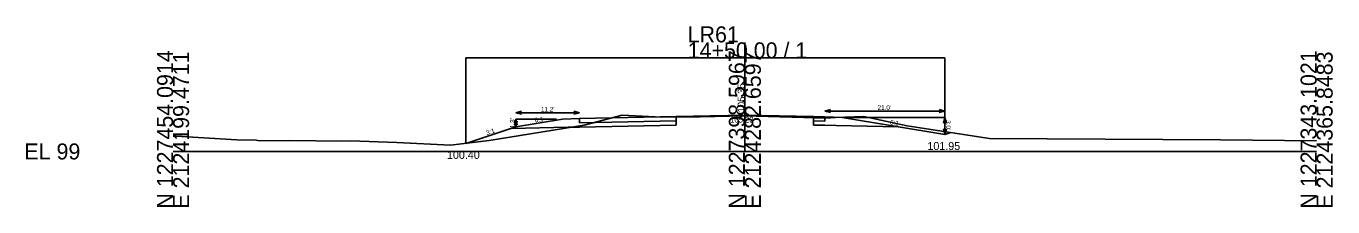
# Model space of a CAD drawing. Extents: x 2126751 to 2128979, y 1225108 to 1234639.
# Drawn here: x 2127750.9 to 2127979.4, y 1229607.5 to 1229639.1 of the extents above; entities that cross this region are included whole.
import ezdxf

# ---------------------------------------------------------------- set-up
doc = ezdxf.new("R2010")
doc.units = 0
for name, color, linetype in [('XS_CELL', 7, 'Continuous'), ('XS_M_DITCH', 7, 'Continuous'), ('XS_P_FINISHED_GRADE', 7, 'Continuous'), ('XS_P_FINISHED_GRADE_ELEV_TX', 7, 'Continuous'), ('XS_P_SUBGRADE_GRANULAR', 7, 'Continuous'), ('XS_P_SUBGRADE_LEVELING', 7, 'Continuous'), ('XS_P_SUBGRADE_PAVEMENT', 7, 'Continuous'), ('XS_P_TX_CLEARZONE', 7, 'Continuous'), ('XS_P_TX_DCH', 7, 'Continuous'), ('XS_P_TX_FS_BS', 7, 'Continuous'), ('XS_X_GROUND', 7, 'Continuous'), ('XS_X_GROUND_TX', 7, 'Continuous')]:
    doc.layers.add(name, color=color, linetype=linetype)

msp = doc.modelspace()

# ---------------------------------------------------------------- linework, layer by layer
at = {"layer": 'XS_CELL'}
for p, q in [((2127876.61, 1229617.21), (2127876.61, 1229636.29)), ((2127776.61, 1229617.21), (2127876.61, 1229617.21)), ((2127876.61, 1229617.21), (2127976.61, 1229617.21))]:
    msp.add_line(p, q, dxfattribs=at)
at = {"layer": 'XS_M_DITCH'}
for p, q in [((2127827.82, 1229618.61), (2127827.82, 1229633.56)), ((2127827.82, 1229633.56), (2127911.61, 1229633.56)), ((2127911.61, 1229633.56), (2127911.61, 1229620.16))]:
    msp.add_line(p, q, dxfattribs=at)
at = {"layer": 'XS_P_FINISHED_GRADE'}
for p, q in [((2127844.71, 1229622.86), (2127836.56, 1229621.51)), ((2127847.72, 1229622.98), (2127844.71, 1229622.86)), ((2127864.61, 1229623.32), (2127847.72, 1229622.98)), ((2127864.61, 1229623.32), (2127876.61, 1229623.56)), ((2127876.61, 1229623.56), (2127888.61, 1229623.32)), ((2127888.61, 1229623.32), (2127890.61, 1229623.28)), ((2127890.61, 1229623.28), (2127893.61, 1229623.16)), ((2127893.61, 1229623.16), (2127911.61, 1229620.16)), ((2127836.56, 1229621.51), (2127827.82, 1229618.61)), ((2127911.61, 1229620.16), (2127912.63, 1229620.5))]:
    msp.add_line(p, q, dxfattribs=at)
at = {"layer": 'XS_P_SUBGRADE_GRANULAR'}
for p, q in [((2127864.61, 1229621.82), (2127864.61, 1229622.57)), ((2127888.61, 1229621.82), (2127888.61, 1229622.57)), ((2127845.72, 1229621.44), (2127835.75, 1229621.24)), ((2127847.72, 1229621.48), (2127845.72, 1229621.44)), ((2127864.61, 1229621.82), (2127847.72, 1229621.48)), ((2127888.61, 1229621.82), (2127890.61, 1229621.78)), ((2127890.61, 1229621.78), (2127892.61, 1229621.74)), ((2127892.61, 1229621.74), (2127903.43, 1229621.52))]:
    msp.add_line(p, q, dxfattribs=at)
at = {"layer": 'XS_P_SUBGRADE_LEVELING'}
for p, q in [((2127864.61, 1229623.32), (2127864.61, 1229623.22)), ((2127864.61, 1229623.22), (2127868.77, 1229623.29)), ((2127868.77, 1229623.29), (2127876.48, 1229623.44)), ((2127876.48, 1229623.44), (2127886.94, 1229623.13)), ((2127886.94, 1229623.13), (2127888.61, 1229623.08)), ((2127888.61, 1229623.32), (2127888.61, 1229623.08))]:
    msp.add_line(p, q, dxfattribs=at)
at = {"layer": 'XS_P_SUBGRADE_PAVEMENT'}
for p, q in [((2127847.72, 1229622.23), (2127847.72, 1229622.98)), ((2127864.61, 1229622.57), (2127847.72, 1229622.23)), ((2127864.61, 1229622.57), (2127864.61, 1229623.22)), ((2127888.61, 1229622.57), (2127888.61, 1229623.08)), ((2127888.61, 1229622.57), (2127890.61, 1229622.53)), ((2127890.61, 1229622.53), (2127890.61, 1229623.28))]:
    msp.add_line(p, q, dxfattribs=at)
at = {"layer": 'XS_P_TX_CLEARZONE'}
for p, q in [((2127836.56, 1229623.98), (2127837.57, 1229624.23)), ((2127847.72, 1229623.98), (2127846.72, 1229624.23)), ((2127890.61, 1229624.28), (2127891.61, 1229624.53)), ((2127890.61, 1229624.28), (2127891.61, 1229624.03)), ((2127890.61, 1229624.28), (2127911.61, 1229624.28)), ((2127911.61, 1229624.28), (2127910.61, 1229624.53)), ((2127911.61, 1229624.28), (2127910.61, 1229624.03)), ((2127836.56, 1229622.86), (2127836.31, 1229621.86)), ((2127836.56, 1229621.51), (2127836.31, 1229622.51)), ((2127836.56, 1229623.98), (2127837.57, 1229623.73)), ((2127847.72, 1229623.98), (2127836.56, 1229623.98)), ((2127836.56, 1229622.86), (2127836.82, 1229621.86)), ((2127836.56, 1229622.86), (2127836.56, 1229621.51)), ((2127843.7, 1229622.86), (2127836.56, 1229622.86)), ((2127836.56, 1229621.51), (2127836.82, 1229622.51)), ((2127847.72, 1229623.98), (2127846.72, 1229623.73)), ((2127894.61, 1229623.16), (2127911.61, 1229623.16)), ((2127911.61, 1229623.16), (2127911.36, 1229622.16)), ((2127911.61, 1229623.16), (2127911.61, 1229620.16)), ((2127911.61, 1229623.16), (2127911.86, 1229622.16)), ((2127911.61, 1229620.16), (2127911.36, 1229621.16)), ((2127911.61, 1229620.16), (2127911.86, 1229621.16))]:
    msp.add_line(p, q, dxfattribs=at)
at = {"layer": 'XS_X_GROUND'}
for p, q in [((2127848.5, 1229621.81), (2127855.18, 1229623.57)), ((2127855.18, 1229623.57), (2127857.51, 1229623.45)), ((2127857.51, 1229623.45), (2127862.08, 1229623.18)), ((2127862.08, 1229623.18), (2127868.77, 1229623.29)), ((2127868.77, 1229623.29), (2127876.48, 1229623.44)), ((2127876.48, 1229623.44), (2127886.94, 1229623.13)), ((2127886.94, 1229623.13), (2127890.69, 1229623.02)), ((2127890.69, 1229623.02), (2127892.47, 1229623.12)), ((2127892.47, 1229623.12), (2127897.4, 1229623.31)), ((2127897.4, 1229623.31), (2127905.01, 1229621.67)), ((2127776.61, 1229619.87), (2127777.15, 1229619.86)), ((2127777.15, 1229619.86), (2127787.74, 1229619.24)), ((2127831.88, 1229619.1), (2127848.5, 1229621.81)), ((2127905.01, 1229621.67), (2127919.37, 1229619.46)), ((2127787.74, 1229619.24), (2127791.16, 1229619.16)), ((2127791.16, 1229619.16), (2127791.71, 1229619.09)), ((2127791.71, 1229619.09), (2127797.01, 1229619.1)), ((2127797.01, 1229619.1), (2127806.14, 1229618.99)), ((2127806.14, 1229618.99), (2127807.62, 1229619.04)), ((2127807.62, 1229619.04), (2127815.74, 1229618.8)), ((2127815.74, 1229618.8), (2127825.15, 1229618.3)), ((2127825.15, 1229618.3), (2127831.88, 1229619.1)), ((2127919.37, 1229619.46), (2127959.8, 1229619.26)), ((2127959.8, 1229619.26), (2127976.61, 1229619.09))]:
    msp.add_line(p, q, dxfattribs=at)

# ---------------------------------------------------------------- texts
at = {"layer": 'XS_CELL'}
for s, p in [('LR61', (2127866.61, 1229636.29)), ('14+50.00 / 1', (2127866.61, 1229633.49)), ('EL 99', (2127750.61, 1229615.81))]:
    msp.add_text(s, height=2.8, dxfattribs=at).set_placement(p)
for s, p in [('N 1227454.0914', (2127776.61, 1229607.21)), ('E 2124199.4711', (2127779.41, 1229607.21)), ('N 1227398.5967', (2127876.61, 1229607.21)), ('E 2124282.6597', (2127879.41, 1229607.21)), ('N 1227343.1021', (2127976.61, 1229607.21)), ('E 2124365.8483', (2127979.41, 1229607.21))]:
    msp.add_text(s, height=2.8, rotation=90, dxfattribs=at).set_placement(p)
at = {"layer": 'XS_P_FINISHED_GRADE_ELEV_TX'}
msp.add_text(' 105.35', height=1.25, rotation=90, dxfattribs=at).set_placement((2127876.61, 1229623.56))
at = {"layer": 'XS_P_TX_CLEARZONE'}
for s, p in [("11.2'", (2127840.96, 1229624.18)), ("21.0'", (2127899.82, 1229624.48))]:
    msp.add_text(s, height=0.8, dxfattribs=at).set_placement(p)
for s, rotation, p in [("1.3'", 90, (2127836.36, 1229621.29)), ("3.0'", 270, (2127911.81, 1229622.68))]:
    msp.add_text(s, height=0.8, rotation=rotation, dxfattribs=at).set_placement(p)
at = {"layer": 'XS_P_TX_DCH'}
for s, p in [('101.95', (2127908.54, 1229617.46)), ('100.40', (2127824.52, 1229615.91))]:
    msp.add_text(s, height=1.4, dxfattribs=at).set_placement(p)
at = {"layer": 'XS_P_TX_FS_BS'}
for s, rotation, p in [('6:1', 9.412, (2127839.91, 1229622.27)), ('6:1', 350.5377, (2127901.95, 1229621.97)), ('3:1', 18.3417, (2127831.49, 1229620.04))]:
    msp.add_text(s, height=0.8, rotation=rotation, dxfattribs=at).set_placement(p)
at = {"layer": 'XS_X_GROUND_TX'}
msp.add_text('105.23', height=1, dxfattribs=at).set_placement((2127874.05, 1229622.27))

doc.saveas('drawing.dxf')
